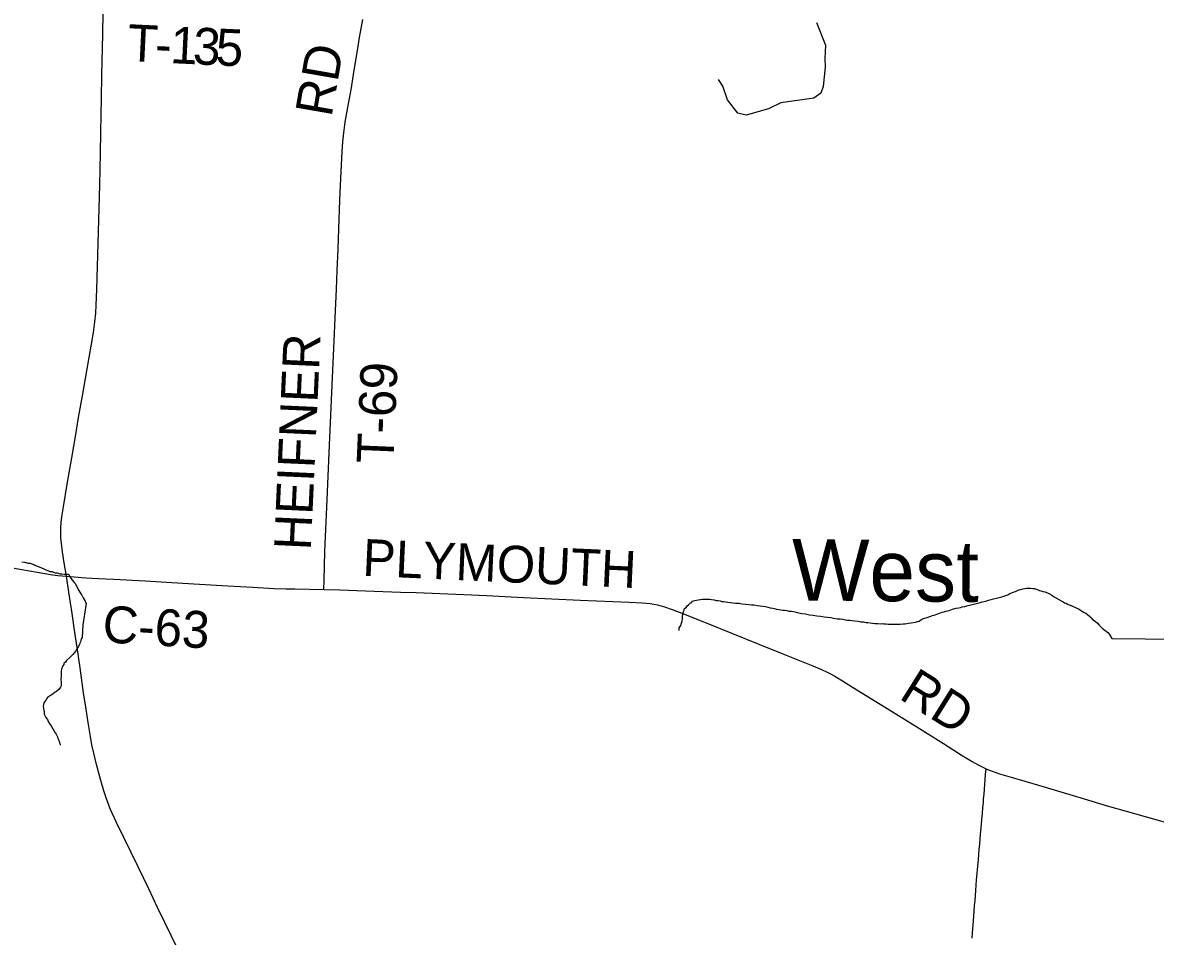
# Model space of a CAD drawing. Extents: x -49 to -8.2, y 9.4 to 23.5.
# Drawn here: x -12.253 to -11.38, y 11.284 to 11.988 of the extents above; entities that cross this region are included whole.
import ezdxf

# ---------------------------------------------------------------- set-up
doc = ezdxf.new("R2010")
doc.units = 0
for name, color, linetype in [('GM_X_County_Road', 7, 'Continuous'), ('GM_X_County_Road_Text', 7, 'Continuous'), ('GM_X_Minor_River', 7, 'Continuous'), ('GM_X_Minor_River_Text', 7, 'Continuous'), ('GM_X_State_Route', 7, 'Continuous'), ('GM_X_Township_Road', 7, 'Continuous'), ('GM_X_Township_Road_Text', 7, 'Continuous')]:
    doc.layers.add(name, color=color, linetype=linetype)

msp = doc.modelspace()

# ---------------------------------------------------------------- linework, layer by layer
at = {"layer": 'GM_X_County_Road'}
for points in [[(-12.31854, 11.57738), (-12.2841, 11.57155), (-12.25411, 11.56635), (-12.24216, 11.56431), (-12.23208, 11.56251), (-12.22625, 11.56168), (-12.21962, 11.56104)], [(-12.21962, 11.56104), (-12.20485, 11.55991), (-12.19492, 11.55941), (-12.18313, 11.55889), (-12.15893, 11.55746), (-12.13847, 11.55621), (-12.11706, 11.55506), (-12.09535, 11.55376), (-12.07613, 11.55264), (-12.0597, 11.5517), (-12.0504, 11.55136), (-12.04357, 11.55127), (-12.02131, 11.5508)], [(-12.02131, 11.5508), (-12.00909, 11.55055), (-11.98921, 11.5499), (-11.9622, 11.54892), (-11.9501, 11.54845), (-11.91346, 11.54695), (-11.89577, 11.54621), (-11.86753, 11.54479), (-11.82379, 11.54265), (-11.78592, 11.54105), (-11.77597, 11.54051), (-11.76976, 11.53995), (-11.76421, 11.53899), (-11.75877, 11.53755), (-11.75287, 11.53553), (-11.74416, 11.53215), (-11.72656, 11.52512), (-11.68595, 11.50869), (-11.66637, 11.50076), (-11.64442, 11.49206), (-11.63782, 11.48926), (-11.63331, 11.48715), (-11.63081, 11.48587), (-11.62753, 11.48406), (-11.62169, 11.48048), (-11.61377, 11.47556), (-11.58919, 11.46039), (-11.56437, 11.445), (-11.54381, 11.43215), (-11.52937, 11.42302), (-11.5217, 11.41832), (-11.51713, 11.41571), (-11.51346, 11.41388), (-11.51094, 11.41273)], [(-11.51094, 11.41273), (-11.50988, 11.41225), (-11.50616, 11.41075), (-11.5006, 11.40884), (-11.49169, 11.40612), (-11.4705, 11.40001), (-11.44133, 11.39125), (-11.4175, 11.38423), (-11.39662, 11.37813), (-11.35472, 11.36651), (-11.32827, 11.35958), (-11.29642, 11.35122), (-11.28921, 11.34936)]]:
    msp.add_lwpolyline(points, dxfattribs=at)
at = {"layer": 'GM_X_Minor_River'}
for points in [[(-11.64159, 11.98773), (-11.6347, 11.97033), (-11.63508, 11.96008), (-11.635, 11.95343), (-11.63641, 11.93846), (-11.63839, 11.93336), (-11.64377, 11.92948), (-11.66903, 11.92595), (-11.67859, 11.92119), (-11.69573, 11.91637), (-11.70233, 11.91801), (-11.7103, 11.92822), (-11.71371, 11.93873), (-11.71703, 11.94391)], [(-12.25399, 11.57227), (-12.2521, 11.57187), (-12.24926, 11.57127), (-12.24774, 11.57106), (-12.24642, 11.57067), (-12.24528, 11.57028), (-12.24397, 11.5695), (-12.24226, 11.56891), (-12.24075, 11.56832), (-12.23905, 11.56754), (-12.23716, 11.56676), (-12.23547, 11.56598), (-12.23395, 11.5654), (-12.23263, 11.56481), (-12.23074, 11.5646), (-12.2296, 11.56421), (-12.22828, 11.56381), (-12.22695, 11.56361), (-12.22601, 11.56341), (-12.22468, 11.56301), (-12.22336, 11.563), (-12.22108, 11.56278), (-12.21918, 11.56276), (-12.21824, 11.56256), (-12.21674, 11.56026), (-12.21506, 11.55778), (-12.21356, 11.55605), (-12.21262, 11.55528), (-12.21152, 11.55242)], [(-12.21152, 11.55242), (-12.21021, 11.55012), (-12.20872, 11.54764), (-12.20797, 11.54649), (-12.20686, 11.54439), (-12.20611, 11.54305), (-12.20537, 11.5419), (-12.205, 11.54094), (-12.20463, 11.53999), (-12.20698, 11.52355)], [(-11.56867, 11.52522), (-11.56715, 11.5254), (-11.56544, 11.52576), (-11.56373, 11.52631), (-11.56259, 11.52648), (-11.56144, 11.52723), (-11.55992, 11.52816), (-11.5582, 11.52871), (-11.5563, 11.52926), (-11.55497, 11.52982), (-11.55363, 11.53018), (-11.55211, 11.53092), (-11.55021, 11.53128), (-11.54887, 11.53184), (-11.54735, 11.53239), (-11.54602, 11.53276), (-11.54469, 11.53331), (-11.54335, 11.53368), (-11.54221, 11.53404), (-11.5405, 11.5344), (-11.53936, 11.53477), (-11.53822, 11.53514), (-11.53669, 11.53569), (-11.53403, 11.53642), (-11.53194, 11.53678), (-11.53061, 11.53695), (-11.52927, 11.53751), (-11.52737, 11.53787), (-11.52566, 11.53823), (-11.52376, 11.53877), (-11.52167, 11.53932), (-11.51615, 11.54059), (-11.51406, 11.54133), (-11.5112, 11.54186), (-11.50911, 11.5426), (-11.50702, 11.54315), (-11.50511, 11.54369), (-11.50302, 11.54424), (-11.50093, 11.54479), (-11.49884, 11.54514), (-11.49712, 11.54569), (-11.4956, 11.54624), (-11.49427, 11.5468), (-11.49274, 11.54773), (-11.49064, 11.54847), (-11.48931, 11.54902), (-11.48836, 11.54939), (-11.48721, 11.54995), (-11.48569, 11.5505), (-11.48417, 11.55087), (-11.48246, 11.55142), (-11.48113, 11.55159), (-11.4798, 11.55177), (-11.47865, 11.55194), (-11.47752, 11.55193), (-11.47657, 11.55192), (-11.47524, 11.55172), (-11.47373, 11.55151), (-11.47278, 11.55131), (-11.47089, 11.55053), (-11.46976, 11.55013), (-11.46862, 11.54974), (-11.46711, 11.54934), (-11.4656, 11.54895), (-11.46352, 11.54835), (-11.46201, 11.54739), (-11.46031, 11.54642), (-11.45843, 11.54526), (-11.45654, 11.5441), (-11.45484, 11.54313), (-11.45315, 11.54216), (-11.45164, 11.54138), (-11.45051, 11.54061), (-11.44918, 11.54021), (-11.44805, 11.53963), (-11.44692, 11.53905), (-11.44541, 11.53846), (-11.4439, 11.53787), (-11.43974, 11.53593), (-11.43824, 11.53496), (-11.43654, 11.53399), (-11.43522, 11.53322), (-11.43409, 11.53263), (-11.43296, 11.53186), (-11.43089, 11.52994), (-11.42995, 11.52898), (-11.42883, 11.52783), (-11.4277, 11.52686), (-11.42657, 11.52628), (-11.42525, 11.52513), (-11.42375, 11.5234), (-11.42262, 11.52225), (-11.4215, 11.52109), (-11.42018, 11.52013), (-11.41924, 11.51936), (-11.4183, 11.51878), (-11.41717, 11.51763), (-11.41586, 11.51628), (-11.41395, 11.51312)], [(-11.74745, 11.51926), (-11.74743, 11.52135), (-11.74608, 11.52304), (-11.74509, 11.52683), (-11.74489, 11.52778), (-11.74488, 11.52911), (-11.74487, 11.53025), (-11.74466, 11.53158), (-11.74446, 11.53271), (-11.74407, 11.53385), (-11.74349, 11.53498), (-11.74347, 11.53631), (-11.74214, 11.53706), (-11.74137, 11.53819), (-11.74022, 11.53912), (-11.73888, 11.54025), (-11.73793, 11.54081), (-11.73716, 11.54175), (-11.73544, 11.5423), (-11.73411, 11.54267), (-11.73278, 11.54284), (-11.73107, 11.5432), (-11.72955, 11.54337), (-11.72784, 11.54335), (-11.72576, 11.54333), (-11.72405, 11.54331), (-11.72253, 11.5431), (-11.72045, 11.54289), (-11.71894, 11.54249), (-11.71742, 11.54229), (-11.7159, 11.54208), (-11.71458, 11.54169), (-11.71326, 11.54148), (-11.71174, 11.54127), (-11.70606, 11.54064), (-11.70397, 11.54043), (-11.70132, 11.54021), (-11.69923, 11.5398), (-11.6962, 11.53958), (-11.69374, 11.53936), (-11.69184, 11.53915), (-11.68976, 11.53894), (-11.6873, 11.53853), (-11.68502, 11.53831), (-11.68294, 11.53791), (-11.68104, 11.5377), (-11.67915, 11.5373), (-11.67726, 11.53671), (-11.67537, 11.53649), (-11.67423, 11.5361), (-11.67234, 11.5357), (-11.67063, 11.53549), (-11.66912, 11.53528), (-11.6676, 11.53489), (-11.66628, 11.53487), (-11.66457, 11.53466), (-11.66287, 11.53426), (-11.66078, 11.53405), (-11.65927, 11.53384), (-11.65719, 11.53344), (-11.65548, 11.53285), (-11.65283, 11.53244), (-11.64999, 11.53203), (-11.64696, 11.53142), (-11.64431, 11.53101), (-11.64128, 11.5306), (-11.63844, 11.53019), (-11.63579, 11.52978), (-11.63313, 11.52956), (-11.63067, 11.52915), (-11.62878, 11.52875), (-11.62556, 11.52833), (-11.62347, 11.52812), (-11.62139, 11.52791), (-11.61949, 11.52751), (-11.61779, 11.5273), (-11.61608, 11.52728), (-11.61438, 11.52688), (-11.6121, 11.52666), (-11.60964, 11.52644), (-11.60737, 11.52604), (-11.60547, 11.52583), (-11.60339, 11.52542), (-11.60206, 11.52541), (-11.59657, 11.52459), (-11.59448, 11.52456), (-11.59259, 11.52435), (-11.59107, 11.52453), (-11.58974, 11.52451), (-11.58785, 11.5243), (-11.58633, 11.52409), (-11.58519, 11.52408), (-11.58367, 11.52406), (-11.58197, 11.52404), (-11.57969, 11.52402), (-11.57722, 11.52418), (-11.57494, 11.52434), (-11.57343, 11.52452), (-11.5721, 11.52469), (-11.57096, 11.52487), (-11.56867, 11.52522)], [(-12.20698, 11.52355), (-12.2077, 11.51387), (-12.20829, 11.51274), (-12.2085, 11.5116), (-12.20891, 11.51046), (-12.2095, 11.50952), (-12.20971, 11.50838), (-12.21069, 11.50669), (-12.21167, 11.50519), (-12.21247, 11.50349), (-12.21344, 11.50236), (-12.2148, 11.50087), (-12.21558, 11.49993), (-12.21674, 11.49881), (-12.21965, 11.49601), (-12.22044, 11.49488), (-12.22179, 11.49395), (-12.22181, 11.493), (-12.2224, 11.49206), (-12.22299, 11.49074), (-12.22339, 11.48961), (-12.22381, 11.48771), (-12.22383, 11.48657), (-12.22386, 11.48524), (-12.22389, 11.48333), (-12.22391, 11.48219), (-12.22393, 11.48124), (-12.22377, 11.47972), (-12.22379, 11.47839), (-12.22382, 11.47667), (-12.22441, 11.47554), (-12.2254, 11.47404), (-12.22733, 11.47236), (-12.22849, 11.47181), (-12.22965, 11.47069), (-12.231, 11.46976), (-12.23196, 11.46921), (-12.23428, 11.46754), (-12.23506, 11.4666), (-12.23565, 11.46547), (-12.23643, 11.46454), (-12.23702, 11.46359), (-12.23743, 11.46227), (-12.23765, 11.46075), (-12.23749, 11.45904), (-12.23713, 11.4577), (-12.23677, 11.45674), (-12.2368, 11.45484), (-12.23571, 11.45215), (-12.2344, 11.45061), (-12.23367, 11.44907), (-12.23256, 11.44715), (-12.23144, 11.44579), (-12.23052, 11.44406), (-12.22941, 11.44214), (-12.2283, 11.44041), (-12.22756, 11.43944), (-12.22701, 11.43829), (-12.22664, 11.43733), (-12.22628, 11.43637), (-12.22592, 11.43504), (-12.22537, 11.43388), (-12.22501, 11.43274), (-12.22465, 11.43178), (-12.22446, 11.43139), (-12.22447, 11.43101)], [(-11.41395, 11.51312), (-11.36268, 11.51245)]]:
    msp.add_lwpolyline(points, dxfattribs=at)
at = {"layer": 'GM_X_State_Route'}
msp.add_lwpolyline([(-12.13356, 11.27313), (-12.1494, 11.30584), (-12.15623, 11.32014), (-12.16452, 11.33718), (-12.16981, 11.34808), (-12.18105, 11.37129), (-12.18442, 11.37861), (-12.18566, 11.38142), (-12.18692, 11.38453), (-12.1891, 11.39042), (-12.19085, 11.39571), (-12.19321, 11.40374), (-12.19652, 11.41604), (-12.19872, 11.42476), (-12.20011, 11.43112), (-12.20128, 11.43753), (-12.20296, 11.44826), (-12.20459, 11.4587), (-12.20648, 11.47129), (-12.20919, 11.49036), (-12.21151, 11.50604), (-12.21316, 11.51772), (-12.21537, 11.53248), (-12.2178, 11.54876), (-12.21962, 11.56104), (-12.22136, 11.57149), (-12.22268, 11.57976), (-12.22357, 11.58652), (-12.22396, 11.59052), (-12.22414, 11.59452), (-12.22408, 11.59822), (-12.22378, 11.60253), (-12.22327, 11.60683), (-12.2221, 11.61449), (-12.21909, 11.63194), (-12.21546, 11.65244), (-12.21252, 11.67022), (-12.2103, 11.68339), (-12.20731, 11.70022), (-12.2039, 11.71949), (-12.20028, 11.74), (-12.19884, 11.7489), (-12.19771, 11.75723), (-12.19706, 11.76374), (-12.1967, 11.76995), (-12.19632, 11.78208), (-12.19389, 11.8624), (-12.19349, 11.88708), (-12.19314, 11.90324), (-12.19289, 11.9166), (-12.19269, 11.92934), (-12.1923, 11.94735), (-12.19165, 11.97873), (-12.19134, 11.9955)], dxfattribs=at)
at = {"layer": 'GM_X_Township_Road'}
for points in [[(-12.02131, 11.5508), (-12.0211, 11.55815), (-12.02046, 11.58019), (-12.01972, 11.59726), (-12.01908, 11.61434), (-12.01807, 11.63824), (-12.01694, 11.66213), (-12.01429, 11.71984), (-12.0133, 11.74219), (-12.01258, 11.76019), (-12.01153, 11.78222), (-12.011, 11.7968), (-12.01031, 11.81326), (-12.00973, 11.82878), (-12.00888, 11.85081), (-12.00816, 11.86757), (-12.00709, 11.88836), (-12.00656, 11.89579), (-12.00583, 11.9029), (-12.00477, 11.91091), (-12.00308, 11.92102), (-12.0001, 11.93753), (-11.99809, 11.94948), (-11.99511, 11.96787), (-11.9938, 11.97615), (-11.99134, 11.99025)], [(-11.52177, 11.28215), (-11.52146, 11.28618), (-11.52099, 11.29206), (-11.52042, 11.29918), (-11.52011, 11.30289), (-11.51976, 11.30722), (-11.51942, 11.31125), (-11.51914, 11.31496), (-11.51882, 11.31898), (-11.51853, 11.32301), (-11.5182, 11.32703), (-11.51778, 11.33198), (-11.51751, 11.33507), (-11.51688, 11.3425), (-11.5165, 11.34683), (-11.5162, 11.35054), (-11.51578, 11.35487), (-11.51511, 11.36229), (-11.51468, 11.36724), (-11.51443, 11.37033), (-11.5141, 11.37373), (-11.51374, 11.37837), (-11.51337, 11.3827), (-11.51304, 11.38673), (-11.51283, 11.38951), (-11.51253, 11.39323), (-11.51129, 11.4084), (-11.51094, 11.41273)]]:
    msp.add_lwpolyline(points, dxfattribs=at)

# ---------------------------------------------------------------- texts
at = {"layer": 'GM_X_County_Road_Text'}
for s, rotation, p in [('PLYMOUTH', 357.403, (-11.99192, 11.5615)), ('C-63', 356.57171, (-12.19243, 11.51024)), ('RD', 327.94227, (-11.57891, 11.46725))]:
    msp.add_text(s, height=0.028409, rotation=rotation, dxfattribs=at).set_placement(p)
at = {"layer": 'GM_X_Minor_River_Text'}
msp.add_text('West', height=0.047348, rotation=359.54842, dxfattribs=at).set_placement((-11.6608, 11.54245))
at = {"layer": 'GM_X_Township_Road_Text'}
for s, height, rotation, p in [('T', 0.02841, 357.22619, (-12.17305, 11.95815)), ('1', 0.02841, 357.24262, (-12.14016, 11.95655)), ('3', 0.02841, 357.26763, (-12.12267, 11.95571)), ('5', 0.02841, 357.3729, (-12.10513, 11.95488)), ('-', 0.02841, 357.23779, (-12.15182, 11.95712)), ('RD', 0.028409, 80.1399, (-12.01547, 11.91429)), ('HEIFNER', 0.028409, 87.39735, (-12.03139, 11.58074)), ('T-69', 0.028409, 87.60117, (-11.96768, 11.64744))]:
    msp.add_text(s, height=height, rotation=rotation, dxfattribs=at).set_placement(p)

doc.saveas('drawing.dxf')
